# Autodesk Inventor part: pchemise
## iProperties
Shininess: 21.0
Length Units: 11269
Angle Units: 11279
Time Units: 11290
Mass Units: 11283
Length Display Precision: 3
Angle Display Precision: 2
Compacted: True
Created: 2001-12
Part Number: pchemise
Material: Par défaut
Document SubType Name: Modélisation
Designer: pichon
Density: 0.0
Volumn: 0.0
Area: 0.0
PropertySet Name: Model Information
Control State: 0
Master: False
Checked Out: False
Author: pichon
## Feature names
1. Extrusion1
2. Révolution1 [Revolution]
3. Révolution2 [Revolution]
4. Congé1 [Fillet]
5. Chanfrein1 [Chamfer]
